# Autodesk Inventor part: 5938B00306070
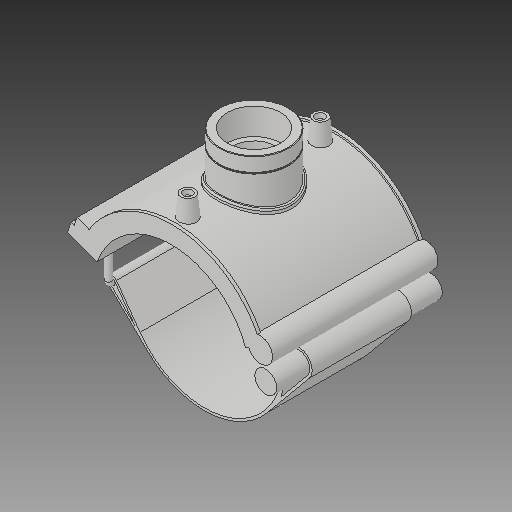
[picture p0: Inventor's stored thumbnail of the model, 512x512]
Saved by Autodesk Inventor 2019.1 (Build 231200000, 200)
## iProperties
Created: 2017-07
Part Number: 5938B00306070
Material: Generic
Description: PLASSON TRANSITION SADDLE 6''IPS x 2"NPT
Document SubType Name: Modeling
Designer: KIM
Density: 1 g/cm^3
Appearance: Default
Author: KIM
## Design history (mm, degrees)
derived "5938B.ipt"
feature "Solid1::5938B.ipt"
tag "TaggingFeature1"
body "Solid1"
other parameters: "d_" = 168, "B_" = 173.736, "H_" = 46.736, "L_" = 176.022, "d_t" = 6, "G_" = 56.656, "d148" = 2.52, "d160" = 2.52, "d169" = 2.52, "d192" = 6.72, "d0" = 168, "d1" = 201.6, "d2" = 434.34, "d3" = 42, "d4" = 176.022, "d5" = 0, "d40" = 104.832, "d41" = 79.3184, "d43" = 0, "d45" = 0, "d47" = 147.536, "d48" = 73.6528, "d50" = 0, "d78" = 122.8, "d79" = 15, "d80" = 70.4088, "d82" = 5 deg, "d84" = 4, "d85" = 14, "d86" = 0, "d87" = 3, "d88" = 0, "d96" = 205.632, "d97" = 3.52044, "d98" = 0, "d102" = 1.69968, "d103" = 56.656, "d104" = 28.0416, "d105" = 0, "d106" = 45.3248, "d108" = 0, "d109" = -15.57867, "d111" = 0.5, "d112" = 0.5, "d113" = 0, "d114" = 0.5, "d117" = 0.56656, "d120" = 140 deg, "d121" = 24.228, "d122" = 20 deg, "d123" = 806.4, "d124" = 120.96, "d126" = 0, "d143" = 173.04, "d145" = 25.84615, "d149" = 2.52, "d150" = 28.43077, "d153" = 176.022, "d154" = 0, "d156" = 100.8, "d157" = 160 deg, "d159" = 6.72, "d161" = 2.52, "d162" = 105.6132, "d163" = 0, "d164" = 84, "d167" = 16.8, "d168" = 98.34146, "d170" = 2.52, "d172" = 0, "d173" = 1, "d175" = 84, "d176" = 20 deg, "d177" = 11.76, "d178" = 33.6, "d180" = 0, "d183" = 13.44, "d184" = 9.408, "d185" = 57.20715, "d186" = 57.20715, "d187" = 100.8, "d188" = 10.08, "d189" = 11.76, "d190" = 0, "d191" = 120.96, "d193" = 6.72, "d194" = 3.444, "d195" = 90 deg, "d197" = 0, "d199" = 0
